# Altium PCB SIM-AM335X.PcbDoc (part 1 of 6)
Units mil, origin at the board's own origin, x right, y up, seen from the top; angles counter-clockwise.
Board outline 4041.51 x 2715.24 mil, 2 copper layers (Top Layer, Bottom Layer); 172 components, 190 nets, 855 pads, 317 vias.
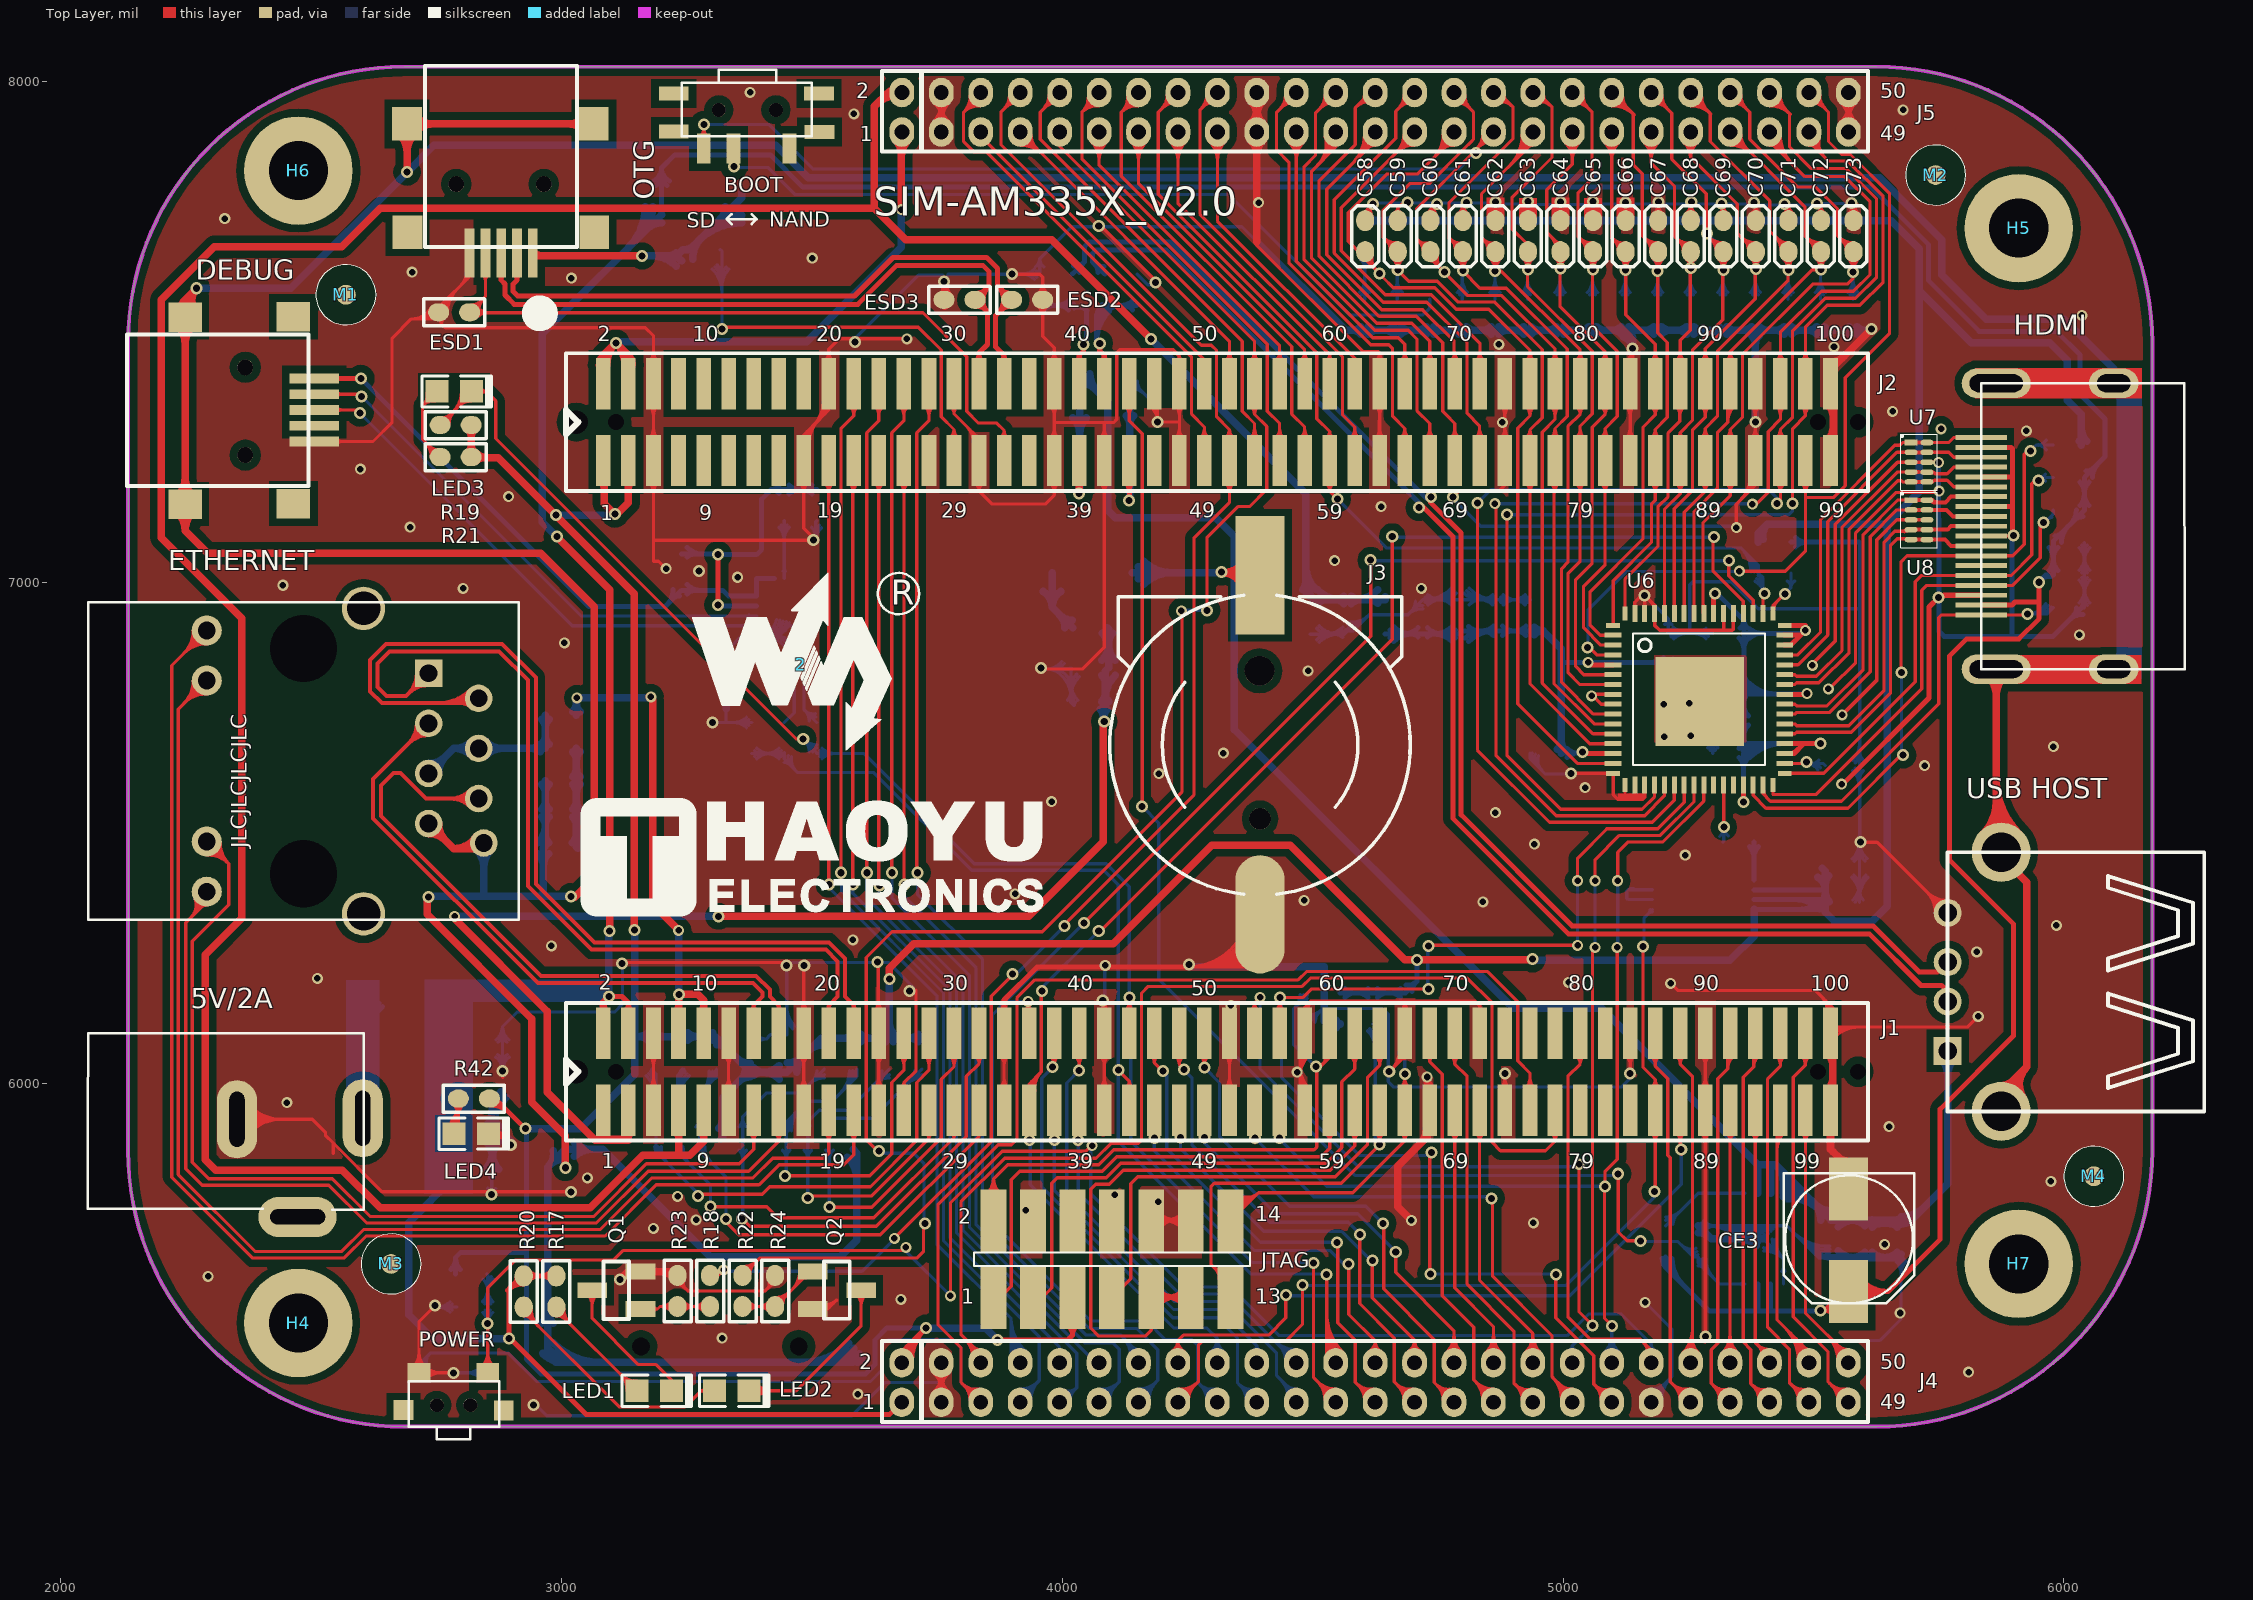
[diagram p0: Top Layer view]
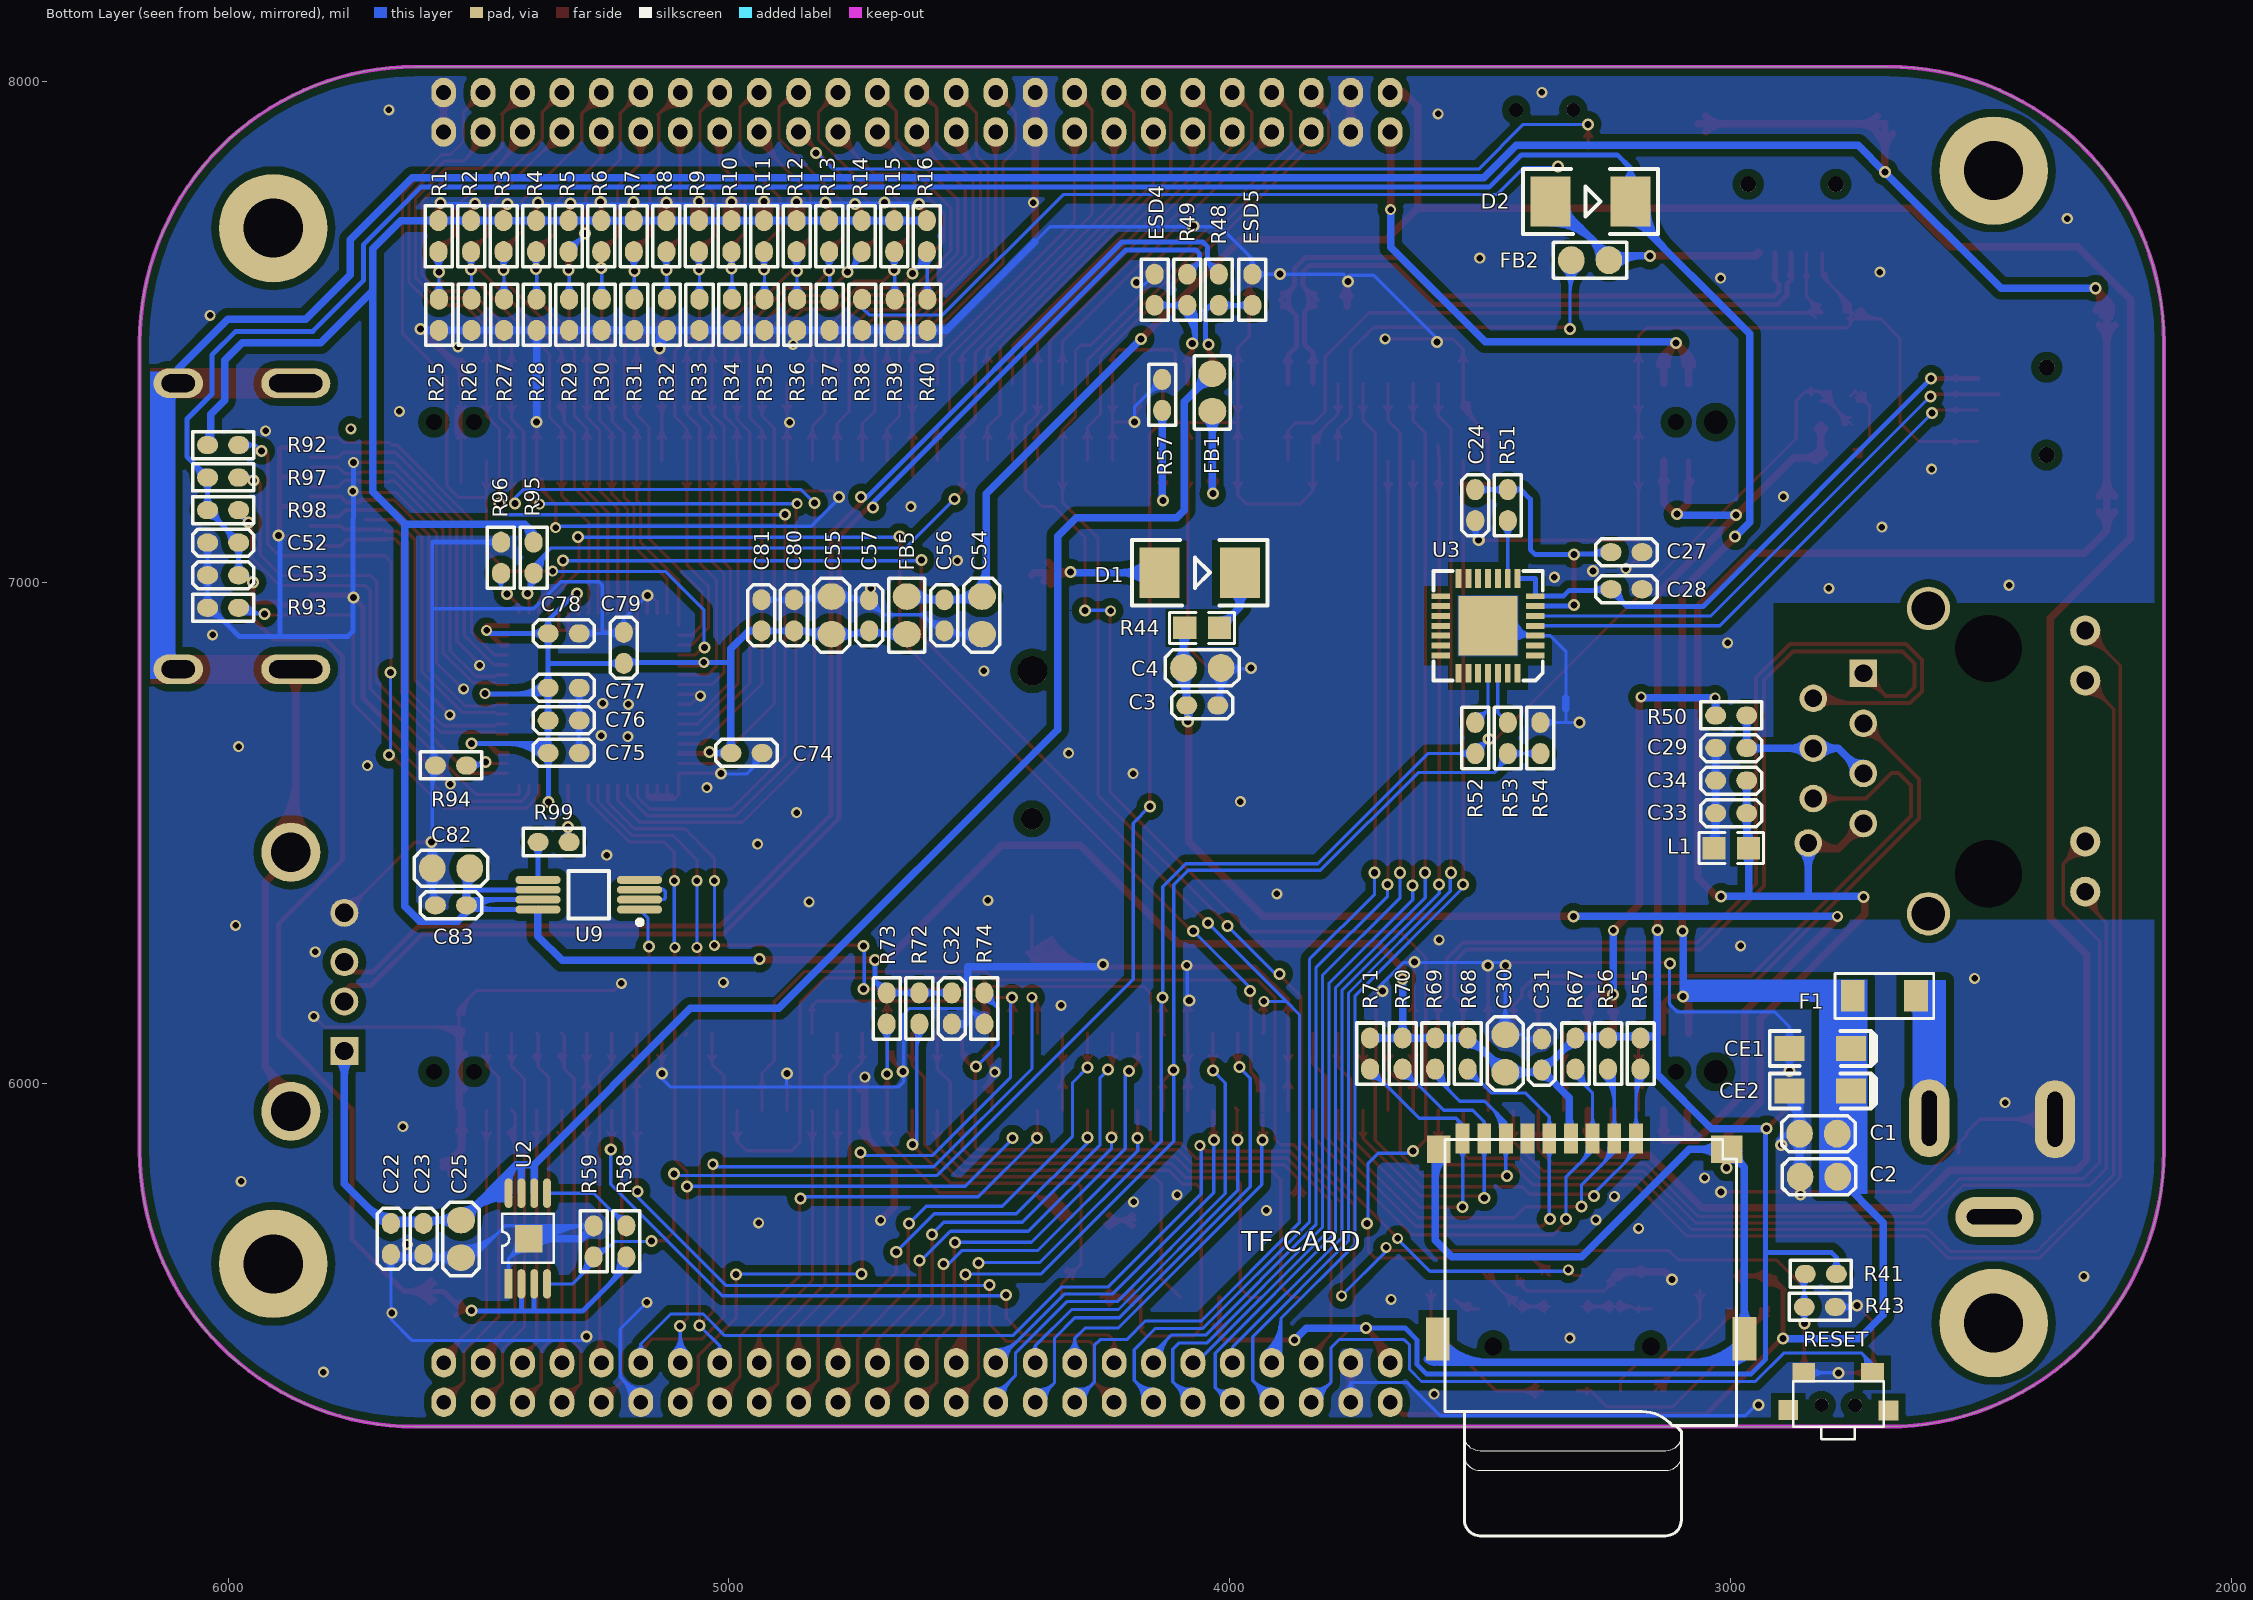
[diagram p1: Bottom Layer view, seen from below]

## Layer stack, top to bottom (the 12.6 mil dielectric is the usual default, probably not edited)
Top Layer: signal copper 1.4
Dielectric: dielectric 12.6, FR-4, Dk 4.8
Bottom Layer: signal copper 1.4

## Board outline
2135,5865 2135,7480.24 cw(c2685,7480.24) 2685,8030.24 5626.51,8030.24 cw(c5626.51,7480.24) 6176.51,7480.24 6176.51,5865 cw(c5626.51,5865) 5626.51,5315 2685,5315 cw(c2685,5865)

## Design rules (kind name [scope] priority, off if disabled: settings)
Clearance Clearance_2 [INPOLYGON] p1: gap=15
Clearance Clearance_1 [ISPAD] p2: gap=1
Clearance gndtoall [inpolygon] p3: gap=15
Clearance [All] p4: gap=6.5
ComponentClearance [All] p1: gap=0 collisioncheckmode=3 verticalgap=0 showdistances=FALSE
DiffPairsRouting USB1_2514 [InDifferentialPair ('USB0')] p1: maxlimit=6.5 minlimit=6.5 mostfreqgap=6.5 maxuncoupledlength=500
DiffPairsRouting YE [InDifferentialPair ('YE')] p2: maxlimit=6.5 minlimit=6.5 mostfreqgap=6.5 maxuncoupledlength=500
DiffPairsRouting USB1 [InDifferentialPair ('USB1')] p3: maxlimit=11 minlimit=6.5 mostfreqgap=10 maxuncoupledlength=500
DiffPairsRouting USB0 [InDifferentialPair ('USB0')] p4: maxlimit=10 minlimit=6.5 mostfreqgap=6.5 maxuncoupledlength=500
DiffPairsRouting PHY_TX [InDifferentialPair ('PHY_TX')] p5: maxlimit=8 minlimit=6.5 mostfreqgap=6.5 maxuncoupledlength=500
DiffPairsRouting PHY_RX [InDifferentialPair ('PHY_RX')] p6: maxlimit=8 minlimit=6.5 mostfreqgap=6.5 maxuncoupledlength=500
DiffPairsRouting HDMI_TXC [InDifferentialPair ('HDMI_TXC')] p7: maxlimit=6.5 minlimit=6.5 mostfreqgap=6.5 maxuncoupledlength=500
DiffPairsRouting HDMI_TX2 [InDifferentialPair ('HDMI_TX2')] p8: maxlimit=6.5 minlimit=6.5 mostfreqgap=6.5 maxuncoupledlength=500
DiffPairsRouting HDMI_TX1 [InDifferentialPair ('HDMI_TX1')] p9: maxlimit=6.5 minlimit=6.5 mostfreqgap=6.5 maxuncoupledlength=500
DiffPairsRouting HDMI_TX0 [InDifferentialPair ('HDMI_TX0')] p10: maxlimit=6.5 minlimit=6.5 mostfreqgap=6.5 maxuncoupledlength=500
DiffPairsRouting GR [InDifferentialPair ('GR')] p11: maxlimit=6.5 minlimit=6.5 mostfreqgap=6.5 maxuncoupledlength=500
DiffPairsRouting DS4 [InDifferentialPair ('DS4')] p12: maxlimit=6.5 minlimit=6.5 mostfreqgap=6.5 maxuncoupledlength=500
DiffPairsRouting DS3 [InDifferentialPair ('DS3')] p13: maxlimit=6.5 minlimit=6.5 mostfreqgap=6.5 maxuncoupledlength=500
DiffPairsRouting DS2 [InDifferentialPair ('DS2')] p14: maxlimit=6.5 minlimit=6.5 mostfreqgap=6.5 maxuncoupledlength=500
DiffPairsRouting DS1 [InDifferentialPair ('DS1')] p15: maxlimit=6.5 minlimit=6.5 mostfreqgap=6.5 maxuncoupledlength=500
DiffPairsRouting [All] p16: maxlimit=10 minlimit=10 mostfreqgap=10 maxuncoupledlength=500
HoleSize [All] p1: absolutevalues=TRUE maxlimit=300 minlimit=1 maxpercent=80.000 minpercent=20.000
HoleToHoleClearance [All] p1: gap=0 allowstackedmicrovias=TRUE
MatchedLengths DiffPair_MatchedLengths [InDifferentialPair ('USB0')] p1: tolerance=1000 checknetsindiffpair=TRUE checkdiffpairvsdiffpair=TRUE checkothers=TRUE
MatchedLengths DiffPair_MatchedLengths_14 [InDifferentialPair ('YE')] p2: tolerance=1000 checknetsindiffpair=TRUE checkdiffpairvsdiffpair=TRUE checkothers=TRUE
MatchedLengths DiffPair_MatchedLengths_1 [InDifferentialPair ('USB1')] p3: tolerance=1000 checknetsindiffpair=TRUE checkdiffpairvsdiffpair=TRUE checkothers=TRUE
MatchedLengths DiffPair_MatchedLengths_2 [InDifferentialPair ('USB0')] p4: tolerance=1000 checknetsindiffpair=TRUE checkdiffpairvsdiffpair=TRUE checkothers=TRUE
MatchedLengths DiffPair_MatchedLengths_3 [InDifferentialPair ('PHY_TX')] p5: tolerance=1000 checknetsindiffpair=TRUE checkdiffpairvsdiffpair=TRUE checkothers=TRUE
MatchedLengths DiffPair_MatchedLengths_4 [InDifferentialPair ('PHY_RX')] p6: tolerance=1000 checknetsindiffpair=TRUE checkdiffpairvsdiffpair=TRUE checkothers=TRUE
MatchedLengths DiffPair_MatchedLengths_5 [InDifferentialPair ('HDMI_TXC')] p7: tolerance=1000 checknetsindiffpair=TRUE checkdiffpairvsdiffpair=TRUE checkothers=TRUE
MatchedLengths DiffPair_MatchedLengths_6 [InDifferentialPair ('HDMI_TX2')] p8: tolerance=1000 checknetsindiffpair=TRUE checkdiffpairvsdiffpair=TRUE checkothers=TRUE
MatchedLengths DiffPair_MatchedLengths_7 [InDifferentialPair ('HDMI_TX1')] p9: tolerance=1000 checknetsindiffpair=TRUE checkdiffpairvsdiffpair=TRUE checkothers=TRUE
MatchedLengths DiffPair_MatchedLengths_8 [InDifferentialPair ('HDMI_TX0')] p10: tolerance=1000 checknetsindiffpair=TRUE checkdiffpairvsdiffpair=TRUE checkothers=TRUE
MatchedLengths DiffPair_MatchedLengths_9 [InDifferentialPair ('GR')] p11: tolerance=1000 checknetsindiffpair=TRUE checkdiffpairvsdiffpair=TRUE checkothers=TRUE
MatchedLengths DiffPair_MatchedLengths_10 [InDifferentialPair ('DS4')] p12: tolerance=1000 checknetsindiffpair=TRUE checkdiffpairvsdiffpair=TRUE checkothers=TRUE
MatchedLengths DiffPair_MatchedLengths_11 [InDifferentialPair ('DS3')] p13: tolerance=1000 checknetsindiffpair=TRUE checkdiffpairvsdiffpair=TRUE checkothers=TRUE
MatchedLengths DiffPair_MatchedLengths_12 [InDifferentialPair ('DS2')] p14: tolerance=1000 checknetsindiffpair=TRUE checkdiffpairvsdiffpair=TRUE checkothers=TRUE
MatchedLengths DiffPair_MatchedLengths_13 [InDifferentialPair ('DS1')] p15: tolerance=1000 checknetsindiffpair=TRUE checkdiffpairvsdiffpair=TRUE checkothers=TRUE
MinimumSolderMaskSliver [All] p1: minsoldermaskwidth=0
PlaneConnect via [IsVia] p1: planeconnectstyle=Direct reliefexpansion=20 reliefentries=4 reliefconductorwidth=10 reliefairgap=10
PlaneConnect [All] p2: planeconnectstyle=Direct reliefexpansion=20 reliefentries=4 reliefconductorwidth=10 reliefairgap=10
PolygonConnect via1 [All vs IsVia] p1: connectstyle=Direct reliefconductorwidth=10 reliefentries=4 polygonreliefangle="90 Angle"
PolygonConnect [All] p2: connectstyle=Direct reliefconductorwidth=10 reliefentries=4 polygonreliefangle="90 Angle"
RoutingVias [All] p1: holewidth=13 width=22 viastyle="Through Hole" minholewidth=13 minwidth=22 maxholewidth=14 maxwidth=25
ShortCircuit [All] p1: allowed=TRUE
SilkToSilkClearance [All] p1: silktosilkclearance=0
SilkscreenOverComponentPads [IsPad] p1: minsilkscreentomaskgap=0
SolderMaskExpansion [All] p1: expansion=4
Width USB_5V [InNet('USB_5V')] p1: maxlimit=15 minlimit=15 preferedwidth=15 minimp=50.000000 maximp=50.000000 favimp=50.000000
Width VDD3V3_USB [InNet('VDD33_USB')] p2: maxlimit=15 minlimit=6.5 preferedwidth=10 minimp=50.000000 maximp=50.000000 favimp=50.000000
Width USB1_2514_Width [InDifferentialPair('USB0')] p3: maxlimit=10 minlimit=6.5 preferedwidth=6.5 minimp=50.000000 maximp=50.000000 favimp=50.000000
Width AUDIO_3V3 [InNet('AUDIO_3V3')] p4: maxlimit=15 minlimit=8 preferedwidth=15 minimp=50.000000 maximp=50.000000 favimp=50.000000
Width VDD_ETH [InNet('VDD_ETH')] p5: maxlimit=15 minlimit=15 preferedwidth=15 minimp=50.000000 maximp=50.000000 favimp=50.000000
Width VDD_3V3A [InNet('VDD_3V3A')] p6: maxlimit=15 minlimit=8 preferedwidth=15 minimp=50.000000 maximp=50.000000 favimp=50.000000
Width USB1_VBUS [InNet('USB1_VBUS')] p7: maxlimit=15 minlimit=6.5 preferedwidth=15 minimp=50.000000 maximp=50.000000 favimp=50.000000
Width HDMI_1V8 [InNet('HDMI_1V8')] p8: maxlimit=15 minlimit=8 preferedwidth=15 minimp=50.000000 maximp=50.000000 favimp=50.000000
Width VCC3V3_BAT [InNet('VCC3V3_BAT')] p9: maxlimit=15 minlimit=15 preferedwidth=15 minimp=50.000000 maximp=50.000000 favimp=50.000000
Width VDD_1V8 [InNet('VDD_1V8')] p10: maxlimit=15 minlimit=8 preferedwidth=15 minimp=50.000000 maximp=50.000000 favimp=50.000000
Width VCC_USB [InNet('VCC_USB')] p11: maxlimit=15 minlimit=15 preferedwidth=15 minimp=50.000000 maximp=50.000000 favimp=50.000000
Width HUB_3V3 [InNet('HUB_3V3')] p12: maxlimit=15 minlimit=15 preferedwidth=15 minimp=50.000000 maximp=50.000000 favimp=50.000000
Width HUB_1V8 [InNet('HUB_1V8')] p13: maxlimit=15 minlimit=8 preferedwidth=15 minimp=50.000000 maximp=50.000000 favimp=50.000000
Width VDD_3V3B [InNet('VDD_3V3B')] p14: maxlimit=15 minlimit=8 preferedwidth=15 minimp=50.000000 maximp=50.000000 favimp=50.000000
Width VDD_5V [InNet('VDD_5V')] p15: maxlimit=15 minlimit=8 preferedwidth=15 minimp=50.000000 maximp=50.000000 favimp=50.000000
Width NETC27 [InNet('NetC27_1')] p16: maxlimit=15 minlimit=15 preferedwidth=15 minimp=50.000000 maximp=50.000000 favimp=50.000000
Width GND_EARTH [InNet('GND_EARTH')] p17: maxlimit=15 minlimit=15 preferedwidth=15 minimp=50.000000 maximp=50.000000 favimp=50.000000
Width YE_Width [InDifferentialPair('YE')] p18: maxlimit=6.5 minlimit=6.5 preferedwidth=6.5 minimp=50.000000 maximp=50.000000 favimp=50.000000
Width USB1_Width [InDifferentialPair('USB1')] p19: maxlimit=10 minlimit=6.5 preferedwidth=10 minimp=50.000000 maximp=50.000000 favimp=50.000000
Width USB0_Width [InDifferentialPair('USB0')] p20: maxlimit=11 minlimit=6.5 preferedwidth=6.5 minimp=50.000000 maximp=50.000000 favimp=50.000000
Width PHY_TX_Width [InDifferentialPair('PHY_TX')] p21: maxlimit=8 minlimit=6.5 preferedwidth=6.5 minimp=50.000000 maximp=50.000000 favimp=50.000000
Width PHY_RX_Width [InDifferentialPair('PHY_RX')] p22: maxlimit=8 minlimit=6.5 preferedwidth=6.5 minimp=50.000000 maximp=50.000000 favimp=50.000000
Width HDMI_TXC_Width [InDifferentialPair('HDMI_TXC')] p23: maxlimit=10 minlimit=6.5 preferedwidth=6.5
Width HDMI_TX2_Width [InDifferentialPair('HDMI_TX2')] p24: maxlimit=10 minlimit=6.5 preferedwidth=6.5
Width HDMI_TX1_Width [InDifferentialPair('HDMI_TX1')] p25: maxlimit=10 minlimit=6.5 preferedwidth=6.5
Width HDMI_TX0_Width [InDifferentialPair('HDMI_TX0')] p26: maxlimit=10 minlimit=6.5 preferedwidth=6.5
Width GR_Width [InDifferentialPair('GR')] p27: maxlimit=6.5 minlimit=6.5 preferedwidth=6.5 minimp=50.000000 maximp=50.000000 favimp=50.000000
Width DS4_Width [InDifferentialPair('DS4')] p28: maxlimit=6.5 minlimit=6.5 preferedwidth=6.5 minimp=50.000000 maximp=50.000000 favimp=50.000000
Width DS3_Width [InDifferentialPair('DS3')] p29: maxlimit=6.5 minlimit=6.5 preferedwidth=6.5 minimp=50.000000 maximp=50.000000 favimp=50.000000
Width DS2_Width [InDifferentialPair('DS2')] p30: maxlimit=6.5 minlimit=6.5 preferedwidth=6.5 minimp=50.000000 maximp=50.000000 favimp=50.000000
Width DS1_Width [InDifferentialPair('DS1')] p31: maxlimit=6.5 minlimit=6.5 preferedwidth=6.5 minimp=50.000000 maximp=50.000000 favimp=50.000000
Width [All] p32: maxlimit=20 minlimit=6.5 preferedwidth=10 minimp=50.000000 maximp=50.000000 favimp=50.000000
19 further rules are at their usual default settings.

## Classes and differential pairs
component class P07_EXT-INTERFACE: 2 H4 J4 J5 M1 M2 M3 M4
component class P06_HDMI: C52 C53 C54 C55 C56 C57 C58 C59 C60 C61 C62 C63 C64 C65 C66 C67 C68 C69 C70 C71 C72 C73 C74 C75 C76 C77 C78 C79 C80 C81 C82 C83 FB5 HDMI R92 R93 R94 R95 R96 R97 R98 R99 U6 U7 U8 U9
component class P04_DEBUG+TF: C24 C27 C28 C29 C30 C31 C32 C33 C34 DEBUG ETHERNET JTAG L1 R50 R51 R52 R53 R54 R55 R56 R58 R59 R67 R70 R71 R72 R73 R74 "TF Card" U2
component class P05_USB_HOST+OTG: C22 C23 C25 CE3 D2 ESD1 ESD2 ESD3 ESD4 ESD5 FB1 FB2 OTG R48 R49 R58 R59 U2 "USB HOST"
component class P03_SYSTEM: 5V/2A BOOT C1 C2 C3 C4 CE1 CE2 D1 F1 J3 LED1 LED2 LED3 LED4 POWER Q1 Q2 R1 R2 R3 R4 R5 R6 R7 R8 R9 R10 R11 R12 R13 R14 R16 R17 R18 R19 R20 R21 R22 R23 R24 R25 R26 R27 R28 R29 R30 R31 R32 R33 R34 R35 R36 R37 R38 R39 R40 R43 R44 RESET S1
component class P02_CM-INTERFACE: J1 J2
differential pair USB2: +USB2_P -USB2_N
differential pair HDMI_TX0: +HDMI_TX0_P -HDMI_TX0_N
differential pair HDMI_TX1: +HDMI_TX1_P -HDMI_TX1_N
differential pair HDMI_TX2: +HDMI_TX2_P -HDMI_TX2_N
differential pair HDMI_TXC: +HDMI_TXC_P -HDMI_TXC_N
differential pair PHY_RX: +PHY_RX_P -PHY_RX_N
differential pair PHY_TX: +PHY_TX_P -PHY_TX_N
differential pair USB0: +USB0_P -USB0_N
differential pair USB1: +USB1_P -USB1_N

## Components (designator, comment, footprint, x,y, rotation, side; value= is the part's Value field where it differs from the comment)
2 "waveshare_logo" WS_symbol_XXL 3478,6836 r0 top
5V/2A "DC_PORT" DC3-3.5 2725,5750 r180 top locked
BOOT "SW1" SWITCH_1 3370,7922 r270 top locked
C1 "0.1uf,6.3V" C0805 2825,5900 r0 bottom
C2 "0.1uf,6.3V" C0805 2824,5814 r0 bottom
C3 "0.1uf,6.3V" C0603 4055,6755 r180 bottom
C4 "10uF,10V" C0805 4055,6830 r0 bottom
C22 "10uF,10V" C0603 5675,5690 r90 bottom
C23 "0.1uf,6.3V" C0603 5610,5690 r270 bottom
C24 "18pF,50V" C0603 3510,7155 r270 bottom
C25 "0.1uf,6.3V" C0805 5535,5690 r270 bottom
C27 "1uf,6.3V" C0603 3208,7061 r180 bottom
C28 "1uf,6.3V" C0603 3208,6987 r180 bottom
C29 "0.022uF,10V" C0603 2999,6670 r0 bottom
C30 "10uF,10V" C0805 3450,6060 r270 bottom
C31 "0.1uf,6.3V" C0603 3377,6058 r90 bottom
C32 "0.1uf,6.3V" C0603 4555,6150 r270 bottom
C33 "0.1uf,6.3V" C0603 2999,6540 r0 bottom
C34 "0.1uf,6.3V" C0603 2999,6605 r0 bottom
C52 "10uF,10V" C0603 6010,7080 r180 bottom
C53 "0.1uf,6.3V" C0603 6010,7015 r0 bottom
C54 "10uF,10V" C0805 4495,6935 r90 bottom
C55 "10uF,10V" C0805 4795,6935 r270 bottom
C56 "0.1uf,6.3V" C0603 4570,6935 r270 bottom
C57 "0.1uf,6.3V" C0603 4720,6935 r90 bottom
C58 "47pf,6.3V" C0603 4605,7692 r90 top
C59 "47pf,6.3V" C0603 4670,7692 r90 top
C60 "47pf,6.3V" C0603 4735,7692 r90 top
C61 "47pf,6.3V" C0603 4800,7692 r90 top
C62 "47pf,6.3V" C0603 4865,7692 r90 top
C63 "47pf,6.3V" C0603 4930,7692 r90 top
C64 "47pf,6.3V" C0603 4995,7692 r90 top
C65 "47pf,6.3V" C0603 5060,7692 r90 top
C66 "47pf,6.3V" C0603 5125,7692 r90 top
C67 "47pf,6.3V" C0603 5190,7692 r90 top
C68 "47pf,6.3V" C0603 5255,7692 r90 top
C69 "47pf,6.3V" C0603 5320,7692 r90 top
C70 "47pf,6.3V" C0603 5385,7692 r90 top
C71 "47pf,6.3V" C0603 5450,7692 r90 top
C72 "47pf,6.3V" C0603 5515,7692 r90 top
C73 "47pf,6.3V" C0603 5580,7692 r90 top
C74 "2.2uF,6.3V" C0603 4965,6660 r180 bottom
C75 "0.1uf,6.3V" C0603 5330,6660 r180 bottom
C76 "2.2uF,6.3V" C0603 5330,6725 r180 bottom
C77 "0.1uf,6.3V" C0603 5330,6790 r180 bottom
C78 "2.2uF,6.3V" C0603 5330,6898.85 r180 bottom
C79 "0.1uf,6.3V" C0603 5210,6870 r90 bottom
C80 "2.2uF,6.3V" C0603 4870,6935 r90 bottom
C81 "0.1uf,6.3V" C0603 4935,6935 r90 bottom
C82 "10uF,10V" C0805 5555,6430 r180 bottom
C83 "0.1uf,6.3V" C0603 5555,6356 r0 bottom
CE1 "10uF,10V" C1206_A 2760,6070 r0 bottom
CE2 "10uF,10V" C1206_A 2760,5985 r0 bottom
CE3 "220uF,6.3V" C63_54 5570,5585 r180 top locked
D1 "IN5819" DO_214AC 4140,7020 r180 bottom
D2 "IN5819" DO_214AC 3360,7761 r180 bottom
DEBUG "USB MICRO B Connector" USB2 2465,7160 r90 top locked
ESD1 "ULCE0505A015FR" R0603#1 2786,7540 r180 top
ESD2 "ULCE0505A015FR" R0603#1 3930,7565 r0 top
ESD3 "ULCE0505A015FR" R0603#1 3795,7565 r180 top
ESD4 "ULCE0505A015FR" R0603#1 4150,7585 r90 bottom
ESD5 "ULCE0505A015FR" R0603#1 3955,7585 r90 bottom
ETHERNET "HR911105A" HY911105H 2485,6644 r90 top locked
F1 "3A" F1206 2630,6175 r0 bottom
FB1 "150OHM800mA" L0805 4035,7380 r270 bottom
FB2 "150OHM800mA" L0805 3280.5,7644 r180 bottom
FB5 "150OHM800mA" L0805 4645,6935 r270 bottom
H4 "HOLE" PAD_M3#1 2535,5575 r0 top locked (schematic designator H3)
H5 "HOLE" PAD_M3#2 6025,7695 r0 top locked (schematic designator H3)
H6 "HOLE" PAD_M3#3 2525,7835 r0 top locked (schematic designator H3)
H7 "HOLE" PAD_M3#4 5985,5725 r0 top locked (schematic designator H3)
HDMI "HDMI_A" HDMI_A 5835,7290 r270 top locked
J1 "CONN RCPT 50x2" SMD50X2A-1.27MM_1 3084,5947 r0 top locked
J2 "CONN RCPT 50x2" SMD50X2A-1.27MM_1 3084,7244 r0 top locked
J3 "3V" CR1220 4395,7015 r180 top locked
J4 "CON_25X2_2.0MM" "Header 25X2 - 2mm" 3679.87,5364 r90 top locked
J5 "CON_25X2_2.0MM" "Header 25X2 - 2mm" 3680,7900 r90 top locked
JTAG "CON2X7" "HEADER 7X2-2MM-SMT" 3863,5573 r90 top
L1 "BLM18PG181SN1" L0603 2964,6470 r0 bottom
LED1 "LED" LED0603 3151.1,5386.73 r0 top
LED2 "LED" LED0603 3306.1,5386.73 r0 top
LED3 "LED" LED0603 2751.51,7382.2 r0 top
LED4 "LED" LED0603 2785.49,5900 r0 top
M1 "MARK" MARK 2570,7575 r0 top
M2 "MARK" MARK 5744,7814 r0 top
M3 "MARK" MARK 2660.02,5639.99 r0 top
M4 "MARK" MARK 6060,5815 r0 top
OTG "USB MICRO B Connector" USB2 2695,7700 r0 top locked
POWER "POWER" KEY_5 2785,5385 r180 top locked
Q1 "NPN 8050" SOT-23 3155,5550 r180 top
Q2 "NPN 8050" SOT-23 3505,5625 r0 top
R1 "100K/NC,1%" R0603#1 5580,7692 r270 bottom
R2 "100K,1%" R0603#1 5515,7692 r270 bottom
R3 "100K/NC,1%" R0603#1 5450,7692 r270 bottom
R4 "100K/NC,1%" R0603#1 5385,7692 r270 bottom
R5 "100K/NC,1%" R0603#1 5320,7692 r270 bottom
R6 "100K/NC,1%" R0603#1 5255,7692 r270 bottom
R7 "100K/NC,1%" R0603#1 5190,7692 r270 bottom
R8 "100K/NC,1%" R0603#1 5125,7692 r270 bottom
R9 "100K/NC,1%" R0603#1 5060,7692 r270 bottom
R10 "100K/NC,1%" R0603#1 4995,7692 r270 bottom
R11 "100K/NC,1%" R0603#1 4930,7692 r270 bottom
R12 "100K,1%" R0603#1 4865,7692 r270 bottom
R13 "100K/NC,1%" R0603#1 4800,7692 r270 bottom
R14 "100K,1%" R0603#1 4735,7692 r270 bottom
R15 "100K,1%" R0603#1 4670,7692 r270 bottom
R16 "100K,1%" R0603#1 4605,7692 r270 bottom
R17 "1K,1%" R0603#1 2990,5585 r90 top
R18 "10K,1%" R0603#1 3296.8,5586 r270 top
R19 "10K,1%" R0603#1 2789,7315 r180 top
R20 "1K,1%" R0603#1 2925,5585 r90 top
R21 "1K,1%" R0603#1 2789,7251 r180 top
R22 "10K,1%" R0603#1 3361.8,5586 r270 top
R23 "10K,1%" R0603#1 3231.8,5586 r270 top
R24 "10K,1%" R0603#1 3426.8,5586 r270 top
R25 "10K,1%" R0603#1 5579,7535 r270 bottom
R26 "10K,1%" R0603#1 5514,7535 r270 bottom
R27 "10K,1%" R0603#1 5449,7535 r270 bottom
R28 "10K,1%" R0603#1 5384,7535 r270 bottom
R29 "10K,1%" R0603#1 5319,7535 r270 bottom
R30 "10K,1%" R0603#1 5254,7535 r270 bottom
R31 "10K,1%" R0603#1 5189,7535 r270 bottom
R32 "10K,1%" R0603#1 5124,7535 r270 bottom
R33 "10K,1%" R0603#1 5059,7535 r270 bottom
R34 "10K,1%" R0603#1 4994,7535 r270 bottom
R35 "10K,1%" R0603#1 4929,7535 r270 bottom
R36 "10K/NC,1%" R0603#1 4864,7535 r270 bottom
R37 "10K,1%" R0603#1 4799,7535 r270 bottom
R38 "10K,1%" R0603#1 4734,7535 r270 bottom
R39 "10K/NC,1%" R0603#1 4669,7535 r270 bottom
R40 "10K/NC,1%" R0603#1 4604,7535 r270 bottom
R41 "10K/NC,1%" R0603#1 2820,5620 r180 bottom
R42 "1K,1%" R0603#1 2825.49,5970 r180 top
R43 "0R/NC,1%" R0603#1 2822,5554 r180 bottom
R44 "100R,1%" R0603#2 4090,6910 r180 bottom
R48 "0R,1%" R0603#1 4022,7585 r270 bottom
R49 "0R,1%" R0603#1 4085,7585 r270 bottom
R50 "0R,1%" R0603#1 2999,6735 r180 bottom
R51 "100K,1%" R0603#1 3445,7155 r270 bottom
R52 "100K,1%" R0603#1 3510,6690 r270 bottom
R53 "100K,1%" R0603#1 3445,6690 r270 bottom
R54 "100K,1%" R0603#1 3380,6690 r90 bottom
R55 "0R,1%" R0603#1 3180,6060 r270 bottom
R56 "12K,1%" R0603#1 3245,6060 r270 bottom
R57 "0R,1%" R0603#1 4135,7375 r270 bottom
R58 "10K,1%" R0603#1 5205,5685 r270 bottom
R59 "10K,1%" R0603#1 5270,5685 r90 bottom
R67 "10K,1%" R0603#1 3310,6060 r270 bottom
R68 "10K,1%" R0603#1 3525,6060 r270 bottom
R69 "10K,1%" R0603#1 3590,6060 r270 bottom
R70 "10K,1%" R0603#1 3655,6060 r270 bottom
R71 "10K,1%" R0603#1 3720,6060 r270 bottom
R72 "4K7,1%" R0603#1 4620,6150 r270 bottom
R73 "4K7,1%" R0603#1 4685,6150 r270 bottom
R74 "4K7K,1%" R0603#1 4490,6150 r90 bottom
R92 "27K,1%" R0603#1 6010,7275 r0 bottom
R93 "47K,1%" R0603#1 6010,6950 r180 bottom
R94 "10K,1%" R0603#1 5555,6635 r180 bottom
R95 "10K,1%" R0603#1 5390,7050 r270 bottom
R96 "0R,1%" R0603#1 5455,7050 r90 bottom
R97 "2K2,1%" R0603#1 6010,7210 r180 bottom
R98 "2K2,1%" R0603#1 6010,7145 r180 bottom
R99 "33" R0603#1 5350,6482.2 r180 bottom
RESET "RESET" KEY_5 2785,5385 r0 bottom locked
"TF CARD" "TF_SD_SOCKET" TF-CARD9 3315,5475 r180 bottom locked (schematic designator "TF Card")
U2 "TPS2051B(DGN)" MSOP-8 5440,5600 r90 bottom
U3 "CP2102" QFN28(5x5) 3390,6855 r0 bottom
U6 "TDA19988" QFN64_9X9 5100,6915 r0 top locked
U7 "SEDFN05V4" SLP2510P8 5695,7280 r0 top
U8 "SEDFN05V4" SLP2510P8 5695,7165 r0 top
U9 "SN74AUC1G74" CFP50P630X90-8N 5280,6377.2 r0 bottom
"USB HOST" "USB-A-DULE" USB-2.0/F 5768,6341 r270 top locked (schematic designator "USB HOST1")

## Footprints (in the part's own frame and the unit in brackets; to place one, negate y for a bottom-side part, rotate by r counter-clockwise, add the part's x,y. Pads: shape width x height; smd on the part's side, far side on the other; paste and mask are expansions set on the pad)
C63_54 [mm]
  rect 2x3.2 smd: 1(0,0) 2(0,-5.2)
  silkscreen extent -3.33,-5.99 3.28,0.61
C0603 [mil]
  oval 42x36 smd: 1(-31,0) 2(31,0)
  silkscreen extent -61,-27 61,27
C0805 [mil]
  oval 53x56 smd: 1(-37.5,0) 2(37.5,0)
  silkscreen extent -74,-36 74,36
C1206_A [mil]
  rect 60x50 smd: 1(0,0) 2(122.5,0)
  silkscreen extent -50,-35 162,35, body extent -2,-32 126,32, height 20
CFP50P630X90-8N [mm] "CFP, 8-Leads, Body 2.40x2.10mm (max), Pitch 0.50mm, IPC Medium Density"
  oval 2.3x0.4 smd: 1(-2.575,0.75) 2(-2.575,0.25) 3(-2.575,-0.25) 4(-2.575,-0.75) 5(2.575,-0.75) 6(2.575,-0.25) 7(2.575,0.25) 8(2.575,0.75)
  silkscreen extent -2.72,-1.2 1.02,1.52, body extent -1.05,-1.2 1.05,1.2, height 0.9
CR1220 [mm]
  round 1.5 hole 1.5 unplated: 0(0.025,4.85)
  round 1.1 hole 1.1 unplated: 0/2(0,12.35)
  rect 2.5x6 smd: 1(0,0)
  oval 2.5x6 smd: 2(0,17.2)
  silkscreen extent -7.62,1.03 7.62,16.17
DC3-3.5 [mil]
  oval 80x156 hole 30 slot 110 at 90 deg: 1(121.53,-180.79) 3(372.53,-178.79)
  oval 156x80 hole 30 slot 110 at 0 deg: 2(251.53,16.2)
  silkscreen extent 119,-351 671,2
DO_214AC [mil]
  rect 80x100 smd: 1(0,0) 2(160,0)
  silkscreen extent -55,-65 215,65
F1206 [mm]
  rect 1.2x1.6 smd: 1(0,0) 2(3.2,0)
  silkscreen extent -0.9,-1.15 4.1,1.15
HDMI_A [mm]
  rect 0.25x2.6 smd: 1(0,0) 2(0.5,0) 3(1,0) 4(1.5,0) 5(2,0) 6(2.5,0) 7(3,0) 8(3.5,0) 9(4,0) 10(4.5,0) 11(5,0) 12(5.5,0) 13(6,0) 14(6.5,0) 15(7,0) 16(7.5,0) 17(8,0) 18(8.5,0) 19(9,0)
  oval 1.5x3.5 hole 0.9 slot 2.7 at 90 deg: 20(11.75,0.76) 21(-2.75,0.76)
  oval 1.5x2.5 hole 0.9 slot 1.7 at 90 deg: 22(-2.75,6.72) 23(11.75,6.72)
  silkscreen extent -2.75,0 11.75,10.31
"HEADER 7X2-2MM-SMT" [mm]
  rect 3.2x1.3 smd: 1(0,0) 2(3.886,0) 3(0,-2) 4(3.883,-2) 5(0,-4) 6(3.883,-4) 7(0,-6) 8(3.883,-6) 9(0,-8.001) 10(3.886,-8.001) 11(0,-10) 12(3.883,-10) 13(0,-12.014) 14(3.886,-12.014)
  silkscreen extent 1.6,-13 2.28,1
"Header 25X2 - 2mm" [mm]
  oval 1.5x1.25 hole 0.75: 1(0,0) 2(2,0) 3(0,-2) 4(2,-2) 5(0,-4) 6(2,-4) 7(0,-6) 8(2,-6) 9(0,-8) 10(2,-8) 11(0,-10) 12(2,-10) 13(0,-12) 14(2,-12) 15(0,-14) 16(2,-14) 17(0,-16) 18(2,-16) 19(0,-18) 20(2,-18) 21(0,-20) 22(2,-20) 23(0,-22) 24(2,-22) 25(0,-24) 26(2,-24) 27(0,-26) 28(2,-26) 29(0,-28) 30(2,-28) 31(0,-30) 32(2,-30) 33(0,-32) 34(2,-32) 35(0,-34) 36(2,-34) 37(0,-36) 38(2,-36) 39(0,-38) 40(2,-38) 41(0,-40) 42(2,-40) 43(0,-42) 44(2,-42) 45(0,-44) 46(2,-44) 47(0,-46) 48(2,-46) 49(0,-48) 50(2,-48)
  silkscreen extent -1,-49 3.1,1
HY911105H [mil]
  rect 55x55 hole 35.43: 1(175.2,-250)
  round 55 hole 35.43: 2(125.2,-350) 3(75.2,-250) 4(25.2,-350) 5(-24.8,-250) 6(-74.8,-350) 7(-124.8,-250) 8(-163.6,-360.2)
  round 60 hole 35.43: 9(260.83,192.91) 10(160.83,192.91) 11(-160.83,192.91) 12(-260.83,192.91)
  round 86.61 hole 66.93: 13(-304.92,-120.08) 14(304.92,-120.08)
  round 129.92 hole 133.86: 15(-225,0) 16(225,0)
  silkscreen extent -317,-430 317,430
KEY_5 [mm]
  rect 1x1 smd: 0(-2.54,0.952) 0(2.54,0.927)
  round 0.7 hole 0.7 unplated: 0(-0.844,0.686) 0(0.858,0.686)
  rect 1.15x1 smd: 1(-1.727,-0.953) 2(1.753,-0.952)
  silkscreen extent -2.31,-0.52 2.29,2.43
L0603 [mil]
  rect 46x45 smd: 1(0,0) 2(69,0)
  silkscreen extent -30,-31 99,31, body extent 3,-17 65,17, height 18
L0805 [mil]
  oval 53x56 smd: 1(-37.5,0) 2(37.5,0)
  silkscreen extent -74,-36 74,36
LED0603 [mil]
  rect 46x45 smd: 1(0,0) 2(69,0)
  silkscreen extent -30,-31 109,31, body extent 3,-17 65,17, height 18
MARK [mm]
  round 1 smd: 1(0,0)
  Top Layer pour cut-out: 1.531,0 1.502,0.299 1.415,0.586 1.273,0.851 1.083,1.083 0.851,1.273 0.586,1.415 0.299,1.502 0,1.531 -0.299,1.502 -0.586,1.415 -0.851,1.273 -1.083,1.083 -1.273,0.851 -1.415,0.586 -1.502,0.299 -1.531,0 -1.502,-0.299 -1.415,-0.586 -1.273,-0.851 -1.083,-1.083 -0.851,-1.273 -0.586,-1.415 -0.299,-1.502 0,-1.531 0.299,-1.502 0.586,-1.415 0.851,-1.273 1.083,-1.083 1.273,-0.851 1.415,-0.586 1.502,-0.299
  silkscreen extent -1.52,-1.52 1.52,1.52
MSOP-8 [mm]
  rect 1.5x0.4 smd: 1(0,0)
  oval 1.5x0.4 smd: 2(0,-0.65) 3(0,-1.3) 4(0,-1.95) 5(4.6,-1.95) 6(4.6,-1.3) 7(4.6,-0.65) 8(4.6,0)
  rect 1.397x1.397 smd: 9(2.286,-1.016)
  silkscreen extent 1.07,-2.29 3.56,0.33
PAD_M3#1 [mm]
  round 5.5 hole 3 unplated: 1(-1.524,-1.346)
PAD_M3#2 [mm]
  round 5.5 hole 3 unplated: 1(-2.921,0.33)
PAD_M3#3 [mm]
  round 5.5 hole 3 unplated: 1(-1.27,-0.305)
PAD_M3#4 [mm]
  round 5.5 hole 3 unplated: 1(-1.905,-2.159)
QFN28(5x5) [mm]
  rect 0.95x0.3 smd: 1(0,0) 2(0,-0.5) 3(0,-1) 4(0,-1.5) 5(0,-2) 6(0,-2.5) 7(0,-3) 15(4.8,-3) 16(4.8,-2.5) 17(4.8,-2) 18(4.8,-1.5) 19(4.8,-1) 20(4.8,-0.5) 21(4.8,0)
  rect 0.3x0.95 smd: 8(0.9,-3.9) 9(1.4,-3.9) 10(1.9,-3.9) 11(2.4,-3.9) 12(2.9,-3.9) 13(3.4,-3.9) 14(3.9,-3.9) 22(3.9,0.9) 23(3.4,0.9) 24(2.9,0.9) 25(2.4,0.9) 26(1.9,0.9) 27(1.4,0.9) 28(0.9,0.9)
  rrect0% 3x3 smd: 29(2.4,-1.499)
  silkscreen extent -0.38,-4.27 5.17,1.27
QFN64_9X9 [mil]
  rect 27.56x10 smd: 1(0,0) 16(0,-295.39) 33(342.63,-295.39) 48(342.63,0)
  rect 33.46x10 smd: 2(0,-19.69) 3(0,-39.39) 4(0,-59.08) 5(0,-78.77) 6(0,-98.46) 7(0,-118.16) 8(0,-137.85) 9(0,-157.54) 10(0,-177.24) 11(0,-196.93) 12(0,-216.62) 13(0,-236.31) 14(0,-256.01) 15(0,-275.7) 34(342.63,-275.7) 35(342.63,-256.01) 36(342.63,-236.31) 37(342.63,-216.62) 38(342.63,-196.93) 39(342.63,-177.24) 40(342.63,-157.54) 41(342.63,-137.85) 42(342.63,-118.16) 43(342.63,-98.46) 44(342.63,-78.77) 45(342.63,-59.08) 46(342.63,-39.39) 47(342.63,-19.69)
  rect 10x27.56 smd: 17(23.62,-319.01) 32(319.01,-319.01) 49(319.01,23.62) 64(23.62,23.62)
  rect 10x33.46 smd: 18(43.31,-319.01) 19(63,-319.01) 20(82.7,-319.01) 21(102.39,-319.01) 22(122.08,-319.01) 23(141.78,-319.01) 24(161.47,-319.01) 25(181.16,-319.01) 26(200.85,-319.01) 27(220.55,-319.01) 28(240.24,-319.01) 29(259.93,-319.01) 30(279.63,-319.01) 31(299.32,-319.01) 50(299.32,23.62) 51(279.63,23.62) 52(259.93,23.62) 53(240.24,23.62) 54(220.55,23.62) 55(200.85,23.62) 56(181.16,23.62) 57(161.47,23.62) 58(141.78,23.62) 59(122.08,23.62) 60(102.39,23.62) 61(82.7,23.62) 62(63,23.62) 63(43.31,23.62)
  rect 177.17x177.17 smd: 65(173,-152)
  silkscreen extent 40,-279 303,-16
R0603#1 [mil]
  oval 42x36 smd: 1(-31,0) 2(31,0)
  silkscreen extent -61,-27 61,27
R0603#2 [mil]
  rect 46x45 smd: 1(0,0) 2(69,0)
  silkscreen extent -30,-31 99,31, body extent 3,-17 65,17, height 18
SLP2510P8 [mm]
  rect 0.65x0.28 smd: 1(0,0)
  oval 0.65x0.28 smd: 2(0,-0.5) 3(0,-1) 4(0,-1.5) 5(0,-2) 6(0.8,-2) 7(0.8,-1.5) 8(0.8,-1) 9(0.8,-0.5) 10(0.8,0)
  silkscreen extent -0.53,-2.41 1.32,0.41
SMD50X2A-1.27MM_1 [mm]
  rect 0.74x2.6 smd: 1(0,0) 2(0,3.9) 3(1.27,0) 4(1.27,3.9) 5(2.54,0) 6(2.54,3.9) 7(3.81,0) 8(3.81,3.9) 9(5.08,0) 10(5.08,3.9) 11(6.35,0) 12(6.35,3.9) 13(7.62,0) 14(7.62,3.9) 15(8.89,0) 16(8.89,3.9) 17(10.16,0) 18(10.16,3.9) 19(11.43,0) 20(11.43,3.9) 21(12.7,0) 22(12.7,3.9) 23(13.97,0) 24(13.97,3.9) 25(15.24,0) 26(15.24,3.9) 27(16.51,0) 28(16.51,3.9) 29(17.78,0) 30(17.78,3.9) 31(19.05,0) 32(19.05,3.9) 33(20.32,0) 34(20.32,3.9) 35(21.59,0) 36(21.59,3.9) 37(22.86,0) 38(22.86,3.9) 39(24.13,0) 40(24.13,3.9) 41(25.4,0) 42(25.4,3.9) 43(26.67,0) 44(26.67,3.9) 45(27.94,0) 46(27.94,3.9) 47(29.21,0) 48(29.21,3.9) 49(30.48,0) 50(30.48,3.9) 51(31.75,0) 52(31.75,3.9) 53(33.02,0) 54(33.02,3.9) 55(34.29,0) 56(34.29,3.9) 57(35.56,0) 58(35.56,3.9) 59(36.83,0) 60(36.83,3.9) 61(38.1,0) 62(38.1,3.9) 63(39.37,0) 64(39.37,3.9) 65(40.64,0) 66(40.64,3.9) 67(41.91,0) 68(41.91,3.9) 69(43.18,0) 70(43.18,3.9) 71(44.45,0) 72(44.45,3.9) 73(45.72,0) 74(45.72,3.9) 75(46.99,0) 76(46.99,3.9) 77(48.26,0) 78(48.26,3.9) 79(49.53,0) 80(49.53,3.9) 81(50.8,0) 82(50.8,3.9) 83(52.07,0) 84(52.07,3.9) 85(53.34,0) 86(53.34,3.9) 87(54.61,0) 88(54.61,3.9) 89(55.88,0) 90(55.88,3.9) 91(57.15,0) 92(57.15,3.9) 93(58.42,0) 94(58.42,3.9) 95(59.69,0) 96(59.69,3.9) 97(60.96,0) 98(60.96,3.9) 99(62.23,0) 100(62.23,3.9)
  round 0 hole 0.8 unplated: 101(0.635,1.95) 102(61.595,1.95) 104(63.63,1.95)
  round 0 hole 1.2 unplated: 103(-1.37,1.95)
  silkscreen extent -1.91,-1.54 64.13,5.44
SOT-23 [mm]
  rect 1.5x0.8 smd: 1(-0.076,0) 2(-0.076,-1.9) 3(2.376,-0.95)
  silkscreen extent 0.5,-2.4 1.8,0.5, body extent -0.64,-2.4 2.95,0.5, height 0.55
SWITCH_1 [mm]
  rect 0.7x1.5 smd: 0(-1.397,3.67) 0(-1.397,-3.696) 0(0.533,-3.696) 0(0.559,3.696)
  round 0.7 hole 0.7 unplated: 0(-0.559,1.486) 0(-0.559,-1.41)
  rect 1.5x0.7 smd: 1(1.397,-2.172) 2(1.397,-0.673) 3(1.397,2.172)
  silkscreen extent -2.59,-3.29 0.79,3.29
TF-CARD9 [mm]
  rect 0.7x1.5 smd: 1(3.2,10.55) 2(2.1,10.55) 3(1,10.55) 4(-0.1,10.55) 5(-1.2,10.55) 6(-2.3,10.55) 7(-3.4,10.55) 8(-4.5,10.55) 9(-5.6,10.55)
  rect 1.2x1.4 smd: 10(-6.8,10)
  rect 1.2x2.2 smd: 11(-6.858,0.381) 13(8.7,0.4)
  rect 1.6x1.4 smd: 12(7.8,10)
  round 0.5 hole 0.9 unplated: 14(-4.04,0.002) 15(3.959,0.003)
  silkscreen extent -6.49,-9.6 8.3,10.5
USB2 [mm]
  round 0.8 hole 0.8: 0(2.413,2.435) 0(6.858,2.435)
  rect 0.5x2.5 smd: 1(6.299,-1.059) 2(5.499,-1.059) 3(4.699,-1.059) 4(3.899,-1.059) 5(3.099,-1.059)
  rect 1.5x1.7 smd: 6(-0.078,5.486) 7(9.4,5.486) 8(-0.053,0) 9(9.425,0)
  silkscreen extent 0.84,-0.76 8.54,8.44, body extent -0.66,-2.31 10.08,8.44, height 4
USB-2.0/F [mm]
  rect 1.42x1.42 hole 0.92: 1(7,0)
  round 1.42 hole 0.92: 2(4.5,0) 3(2.5,0) 4(0,0)
  round 3 hole 2: 5(-3.07,2.71) 6(10.07,2.71)
  silkscreen extent -3.07,0 10.09,13.01
WS_symbol_XXL [mil]
  silkscreen extent -217,-170 237,184

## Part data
5V/2A: library part DC_0
C1 C2 C3 C23 C24 C25 C27 C28 C31 C32 C33 C34 C53 C56 C57 C58 C59 C60 C61 C62 C63 C64 C65 C66 C67 C68 C69 C70 C71 C72 C73 C75 C77 C79 C81 C83: library part "CAP_0.1uF_X5R_6.3V_20% 0201"
C4 C22 C30 C52 C54 C55 C82: library part CAP_10uF_Y5V_10V_10%_0805
C29: library part CAP_0402_0.1uf_X5R_10V
C74 C76 C78 C80: library part CAP_2.2uF_X5R_6.3V_10%_0402
CE1 CE2 CE3: library part CD6.3/2.5
DEBUG OTG: "CONN MICRO_B SMT AU"
ETHERNET: library part "J00-0061 PULSE_0"
F1: library part FUSE
FB1 FB2: library part FER_180_200_0, "Ferrite Bead 150 Ohm 800mA"
FB5: library part FER_180_200_0805, "Ferrite Bead 150 Ohm 800mA"
H4 H5 H6 H7: library part "TEST POINT"
J3: library part BATERY
J4 J5: library part "Header 25X2", "Header, 25-Pin, Dual row"
L1: library part INDUCTOR
M1 M2 M3 M4: library part TEST
POWER RESET: library part KEY
Q1 Q2: library part NPN_SOT23
R1 R2 R3 R4 R5 R6 R7 R8 R9 R10 R11 R12 R13 R14 R15 R16 R25 R26 R27 R28 R29 R30 R31 R32 R33 R34 R35 R36 R37 R38 R39 R40 R50 R51 R54 R55 R56 R58 R59 R67 R68 R69 R70 R71 R72 R73 R74: library part RES_100K_1/16W_1%_0402, "Resistor 100Kohm 1/16W 1% 0402"
R17 R18 R19 R20 R21 R22 R23 R24 R41 R42 R43 R44 R48 R49 R57: library part RES_4.75K_1/16W_1%_0402, "RES 4.75K OHM 1/16W 1% 0402 SMD"
R52 R53 R92 R93 R94 R95 R96: library part RES_10K_1/16W_1%_0402, "Resistor 10Kohm 1/16W 1% 0402"
R97 R98: library part RES_1.5K_1/16W_5%_0402, "RES 1.5K OHM 1/16W 5% 0402 SMD"
R99: library part RES_33_0402
"TF CARD": library part SD_SOCKET_0
U9: library part IC_SN74AUC1G74
"USB HOST": library part "USB HOST"

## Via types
v1: diameter 24, hole 14, Top Layer to Bottom Layer, tented both sides, 206 vias
v2: diameter 22, hole 13, Top Layer to Bottom Layer, tented both sides, 109 vias
v3: diameter 22, hole 14, Top Layer to Bottom Layer, tented both sides, 2 vias

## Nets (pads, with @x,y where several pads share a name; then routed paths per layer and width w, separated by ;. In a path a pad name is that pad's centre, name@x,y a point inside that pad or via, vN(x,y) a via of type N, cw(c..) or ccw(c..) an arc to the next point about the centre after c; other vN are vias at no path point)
AIN0: J1.92 J4.43 | length 933.1
  Top Layer w6.5: 5298.46,5398.95 ccw(c5322.19,5422.68) J4.43@5329.05,5389.83 ; 5300.43,5396.98 cw(c5272.38,5368.92) J4.43@5312.05,5368.92 ; 5306.96,5390.45 ccw(c5325.13,5408.61) J4.43@5330.37,5383.46 ; 5311.53,5385.88 cw(c5294.57,5368.92) J4.43@5318.55,5368.92 ; J1.92@5326,6055.93 cw(c5318.75,6048.68) 5329,6048.68 ; 5329,6029.64 cw(c5361.88,6029.64) J1.92@5341.14,6055.15 ; 5329,6043.3 cw(c5350.77,6043.3) J1.92@5337.04,6060.19 ; J4.43@5333.41,5364 5296,5401.41 5296,5468.24 5309,5481.24 5309,6010 5329,6030 5329,6095.54 J1.92@5334,6100.54
AIN1: J1.91 J4.44 | length 684.7
  Top Layer w6.5: J4.44@5318.31,5462.76 ccw(c5281.85,5499.22) 5333.41,5499.22 ccw(c5384.97,5499.22) J4.44@5348.51,5462.76 ; J4.44@5322.91,5458.17 ccw(c5297.54,5483.53) 5333.41,5483.53 ccw(c5369.28,5483.53) J4.44@5343.91,5458.17 ; J1.91@5326,5902.38 cw(c5308.1,5884.49) 5333.41,5884.49 ; J4.44@5333.41,5442.74 5333.41,5946.41 J1.91@5334,5947 ; 5333.41,5881.64 cw(c5362.75,5881.64) J1.91@5342,5902.38
AIN2: J1.94 J4.45 | length 928.6
  Top Layer w6.5: J1.94@5376,6055.93 cw(c5363.92,6043.85) 5381,6043.85 ; 5377.46,5398.69 ccw(c5400.71,5421.94) J4.45@5407.65,5389.8 ; 5379.17,5396.98 cw(c5351.12,5368.92) J4.45@5390.79,5368.92 ; 5381,6033.85 cw(c5408.44,6033.85) J1.94@5391.14,6055.15 ; 5381,6047.51 cw(c5397.34,6047.51) J1.94@5387.04,6060.19 ; J1.94@5384,6100.54 5381,6097.54 5381,6034 5359.68,6012.68 5359.68,5484.32 5375,5469 5375,5401.15 J4.45@5412.15,5364 ; 5385.9,5390.25 ccw(c5403.71,5408.06) J4.45@5409.02,5383.44 ; 5390.27,5385.88 cw(c5373.31,5368.92) J4.45@5397.29,5368.92
AIN3: J1.93 J4.46 | length 637.4
  Top Layer w6.5: J1.93@5376,5902.38 cw(c5356.68,5883.06) 5384,5883.06 cw(c5411.32,5883.06) J1.93@5392,5902.38 ; J1.93@5384,5947 5384,5483 5412.15,5454.85 J4.46@5412.15,5442.74 ; 5387.96,5479.04 ccw(c5412.15,5503.22) J4.46@5412.15,5469.02 ; 5389.09,5477.91 cw(c5367.36,5456.17) J4.46@5397.56,5450.44 ; 5397.78,5469.22 cw(c5381.96,5453.4) J4.46@5403.94,5449.22
AIN4: J1.96 J4.47 | length 937.4
  Top Layer w6.5: J1.96@5426,6055.93 cw(c5406.68,6036.61) 5434,6036.61 cw(c5461.32,6036.61) J1.96@5442,6055.93 ; J1.96@5434,6100.54 5434,6035 5408.32,6009.32 5408.32,5513.68 5452,5470 5452,5402.89 J4.47@5490.89,5364 ; 5454.46,5400.43 ccw(c5480.99,5426.96) J4.47@5487.3,5389.97 ; 5457.91,5396.98 cw(c5429.86,5368.92) J4.47@5469.53,5368.92 ; 5463.35,5391.54 ccw(c5483.58,5411.77) J4.47@5488.39,5383.57 ; 5469.01,5385.88 cw(c5452.05,5368.92) J4.47@5476.03,5368.92
AIN5: J1.95 J4.48 | length 845.1
  Top Layer w6.5: 5427,5866.16 cw(c5478.22,5866.16) J1.95@5442,5902.38 ; 5427,5881.86 cw(c5462.53,5881.86) J1.95@5437.41,5906.98 ; J1.95@5427,5897.55 cw(c5446.84,5897.55) J1.95@5432.81,5911.58 ; J1.95@5434,5947 5427,5940 5427,5529 5490.89,5465.11 J4.48@5490.89,5442.74 ; 5442.09,5513.91 cw(c5375.85,5447.66) J4.48@5469.53,5447.66 ; 5453.19,5502.81 cw(c5398.04,5447.66) J4.48@5476.03,5447.66 ; 5464.29,5491.71 cw(c5420.23,5447.66) J4.48@5482.53,5447.66 ; 5475.38,5480.62 cw(c5442.43,5447.66) J4.48@5489.03,5447.66 ; 5484.22,5471.78 ccw(c5490.89,5478.45) J4.48@5490.89,5469.02
AIN6: J1.98 J4.49 | length 952
  Top Layer w6.5: J1.98@5476,6055.93 cw(c5457.88,6037.81) 5483.5,6037.81 ; J1.98@5484,6100.54 5483.5,6100.05 5483.5,6036.5 ; J1.98@5491.77,6055.71 ccw(c5509.94,6036.5) 5483.5,6036.5 ; 5531.46,5402.17 ccw(c5561.44,5432.15) J4.49@5566.89,5390.1 ; 5536.65,5396.98 cw(c5508.6,5368.92) J4.49@5548.27,5368.92 ; 5540.81,5392.82 ccw(c5563.58,5415.6) J4.49@5567.72,5383.65 ; 5547.75,5385.88 cw(c5530.79,5368.92) J4.49@5554.77,5368.92 ; J4.49@5569.63,5364 5529,5404.63 5529,5464.99 5459.68,5534.3 5459.68,6012.68 5483.5,6036.5
AIN7: J1.97 J4.50 | length 740.7
  Top Layer w6.5: J1.97@5476,5902.38 cw(c5456.68,5883.06) 5484,5883.06 cw(c5511.32,5883.06) J1.97@5492,5902.38 ; J1.97@5484,5947 5484,5542 5569.63,5456.37 J4.50@5569.63,5442.74 ; 5527.01,5498.99 cw(c5475.69,5447.66) J4.50@5548.27,5447.66 ; 5538.11,5487.89 cw(c5497.88,5447.66) J4.50@5554.77,5447.66 ; 5548.04,5477.96 ccw(c5569.63,5499.55) J4.50@5569.63,5469.02 ; 5549.21,5476.79 cw(c5520.07,5447.66) J4.50@5561.27,5447.66
DCAN1_RX: J1.45 J4.26 | length 883.8
  Top Layer w6.5: J1.45@4178.44,5900.53 cw(c4173.06,5891) v1(4184,5891) ; v1@4184,5889 v1(4184,5891) ; J1.45@4184,5947 v1(4184,5891) ; J1.45@4189.56,5900.53 ccw(c4194.94,5891) v1(4184,5891) ; v1(4572,5640) 4572,5539 4624.75,5486.25 ; J4.26@4613.41,5465.76 ccw(c4600.56,5486.25) 4624.75,5486.25 ; J4.26@4616.86,5460.25 ccw(c4607.92,5474.51) 4624.75,5474.51 ccw(c4641.57,5474.51) J4.26@4632.64,5460.25 ; J4.26@4624.75,5442.74 4624.75,5486.25 ; J4.26@4636.09,5465.76 cw(c4648.93,5486.25) 4624.75,5486.25
  Bottom Layer w6.5: v1@4184,5882 4184,5866 4383,5667 4534.24,5667 4561.24,5640 v1(4572,5640) v1@4575,5640
DCAN1_TX: J1.46 J4.25 | length 1148.3
  Top Layer w6.5: J1.46@4177.44,6054.71 cw(c4168.41,6042) 4184,6042 ; J1.46@4184,6100.54 4184,6042 ; J1.46@4190.56,6054.71 ccw(c4199.59,6042) 4184,6042 ; v1(4201,6025) 4184,6042 ; v1@4550.25,5677.75 4550.25,5522.75 4585,5488 4585,5403.75 J4.25@4624.75,5364 ; 4587.46,5401.29 ccw(c4615.67,5429.5) J4.25@4621.58,5390.04 ; 4591.77,5396.98 cw(c4563.71,5368.92) J4.25@4603.39,5368.92 ; 4596.58,5392.17 ccw(c4618.05,5413.64) J4.25@4622.55,5383.61 ; 4602.87,5385.88 cw(c4585.91,5368.92) J4.25@4609.89,5368.92
  Bottom Layer w6.5: v1(4201,6025) 4209,6017 4209,5870 4396,5683 v1(4549,5683)
DEBUG_N: DEBUG.2 U3.5 | length 1141.6
  Top Layer w6.5: DEBUG.2@2463.5,7376.5 DEBUG.2@2506.69,7376.5 v1@2596.5,7376.5 ; DEBUG.2@2550.72,7371.83 cw(c2561.97,7360.58) 2561.97,7376.5 cw(c2561.97,7392.41) DEBUG.2@2550.72,7381.16
  Bottom Layer w6.5: v1@2598,7372 v1(2601,7372) 3039.26,6933.74 U3.5@3390,6933.74 ; U3.5@3375.33,6931.86 ccw(c3370.79,6927.33) 3370.79,6933.74 ccw(c3370.79,6940.15) U3.5@3375.33,6935.62
DEBUG_P: DEBUG.3 U3.4 | length 1097.5
  Top Layer w6.5: DEBUG.3@2506.69,7345 2592,7345 v1(2598,7339) ; DEBUG.3@2550.72,7340.34 cw(c2561.97,7329.08) 2561.97,7345 cw(c2561.97,7360.92) DEBUG.3@2550.72,7349.66
  Bottom Layer w6.5: v1(2598,7339) 2598,7338 3021.94,6914.06 U3.4@3390,6914.06 ; U3.4@3375.33,6912.18 ccw(c3370.79,6907.65) 3370.79,6914.06 ccw(c3370.79,6920.47) U3.4@3375.33,6915.93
